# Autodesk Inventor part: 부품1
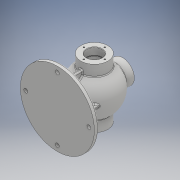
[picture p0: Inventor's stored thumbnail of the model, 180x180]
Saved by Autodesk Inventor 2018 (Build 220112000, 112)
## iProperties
Created: 2020-08
Part Number: 부품1
Material: Generic
Document SubType Name: Modeling
Designer: Administrator
Density: 1 g/cm^3
Appearance: Default
Author: Administrator
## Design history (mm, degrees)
sketch "스케치1"
  geometry: L1 (-85, 0)-(-85, 85); L2 (-85, 85)-(-75, 85); L3 (-75, 85)-(-75, 0); L4 (-75, 0)-(-85, 0); L5 (53, 0)-(-53, 0); A1 r 53 centre (0, 0) between (53, 0) and (-53, 0); 1 further point
  constraints: 10 end point, 2 horizontal, 2 point on circle, 1 centre point, 1 coincident, 1 perpendicular, 1 vertical
  dimensions: "d2" = 85 distance of L1.start L1.end; "d3" = 10 distance of L1.end L2.end
revolve "회전1" sketch "스케치1" stored, may be unused: angle "d4" = 90 deg
sketch "스케치2"
  geometry: L1 (0, 68)-(31, 68); L2 (31, 68)-(31, -68); L3 (31, -68)-(0, -68); L4 (0, 68)-(0, -68); 1 further point
  constraints: 8 end point, 2 perpendicular, 1 vertical
revolve "회전2" sketch "스케치2" stored, may be unused: angle "d9" = 90 deg
sketch "스케치3"
  geometry: L1 (85, -75)-(-85, -75) reference; L2 (43, -75)-(-43, -75); L3 (-43, -75)-(-43, 0); L4 (-43, 0)-(43, 0); L5 (43, 0)-(43, -75); 1 further point
  constraints: 8 end point, 3 perpendicular, 1 point on line
extrude "돌출1" join sketch "스케치3" stored distance "d12" = 8; taper "d13" = 0 deg
sketch "스케치4"
  geometry: L1 (-75, -85)-(-75, 85) reference; L2 (-75, -43.012)-(-75, 43); L3 (-75, 43)-(3.544, 42.988); L4 (-31, 42.988)-(31, 42.988) reference; L5 (3.544, 42.988)-(3.544, -43.012); L6 (3.544, -43.012)-(-75, -43.012); A1 r 4.279 centre (3.544, 38.71) between (3.543, 34.431) and (3.544, 42.988); A2 r 4.279 centre (3.544, 38.71) between (3.544, 42.988) and (3.543, 34.431); 1 further point
  constraints: 8 end point, 4 point on circle, 3 point on line, 3 tangent, 2 centre point, 2 perpendicular
extrude "돌출2" join sketch "스케치4" stored distance "d17" = 8; taper "d18" = 0 deg
sketch "스케치5"
  geometry: L1 (43, 0)-(-43, 0); A1 r 43 centre (0, 0) between (43, 0) and (-43, 0); 1 further point
  constraints: 2 end point, 2 point on circle, 1 centre point, 1 coincident, 1 horizontal
revolve "회전3" sketch "스케치5" stored, may be unused: angle "d20" = 90 deg
sketch "스케치6"
  geometry: L1 (0, 74.444)-(17.5, 74.444); L2 (17.5, 74.444)-(17.5, -78.998); L3 (17.5, -78.998)-(0, -78.998); L4 (0, 74.444)-(0, -78.998); 1 further point
  constraints: 8 end point, 1 perpendicular, 1 vertical
revolve "회전4" sketch "스케치6" stored, may be unused: angle "d23" = 90 deg
sketch "스케치7"
  geometry: L1 (0, 52)-(18.5, 52); L2 (18.5, 52)-(18.5, 50.25); L3 (18.5, 50.25)-(0, 50.25); L4 (0, 50.25)-(0, 52); L5 (0, -52)-(18.5, -52); L6 (18.5, -52)-(18.5, -50.25); L7 (18.5, -50.25)-(0, -50.25); L8 (0, -50.25)-(0, -52); 1 further point
  constraints: 16 end point, 2 perpendicular, 1 horizontal
revolve "회전5" sketch "스케치7" stored, may be unused: angle "d27" = 90 deg
node "작업 평면1"
sketch "스케치8"
  geometry: C1 r 27 at (0, 0); 1 further point
  constraints: 1 centre point, 1 coincident
  dimensions: "d28" = 54 diameter of C1
extrude "돌출3" join sketch "스케치8" stored distance "d29" = 80; taper "d30" = 0 deg
sketch "스케치9"
  geometry: L1 (0, 65)-(-39.777, 65); L2 (-39.777, 65)-(-39.777, 103.189); L3 (-39.777, 103.189)-(41.506, 103.189); L4 (41.506, 103.189)-(41.506, 65); L5 (41.506, 65)-(0, 65); 1 further point
  constraints: 10 end point, 4 perpendicular, 1 horizontal, 1 point on line
  dimensions: "d32" = 81.28308 distance between parallel lines of L2 L4; "d33" = 38.18916 distance between parallel lines of L5 L3; "d34" = 41.50625 distance from line of point (0, 0) L4; "d35" = 65 distance from line of point (0, 0) L5; "d36" = 41.50625 distance from line of L1.start L4
extrude "돌출4" cut sketch "스케치9" distance "d37" = 100; taper "d38" = 0 deg
sketch "스케치10"
  geometry: C1 r 13 at (0, 0); 1 further point
  constraints: 1 centre point, 1 coincident
  dimensions: "d39" = 26 diameter of C1
extrude "돌출5" cut sketch "스케치10" distance "d40" = 50; taper "d41" = 0 deg
sketch "스케치11"
  geometry: C1 r 2 at (-20, 0); 1 further point
  constraints: 1 centre point
  dimensions: "d43" = 4 diameter of C1
hole "구멍1" sketch "스케치11" at (-20, 0) diameter "d44" = 3.242; stored, may be unused: countersink angle "d48" = 90 deg, drill point angle "d50" = 118 deg; dims "d45" = 12, "d46" = 4, "d47" = 2, "d49" = 15
sketch "스케치12"
  geometry: L1 (43, 0)-(-43, 0); A1 r 43 centre (0, 0) between (43, 0) and (-43, 0); 1 further point
  constraints: 2 end point, 2 point on circle, 1 centre point, 1 coincident, 1 horizontal
revolve "회전6" sketch "스케치12" stored, may be unused: angle "d54" = 350 deg
sketch "스케치13"
  geometry: C1 r 4.5 at (-72.5, 0); 2 further points
  constraints: 1 centre point
  dimensions: "d56" = 9 diameter of C1
extrude "돌출6" cut sketch "스케치13" distance "d57" = 50; taper "d58" = 0 deg
sketch "스케치14"
  geometry: L1 (-75, 4)-(-75, -4) reference; L2 (-75, -52)-(-75, 52); L3 (-75, 52)-(-25.941, 52); L4 (-25.941, 52)-(-25.941, -52); L5 (-25.941, -52)-(-75, -52); 1 further point
  constraints: 8 end point, 2 perpendicular, 1 collinear, 1 horizontal
  dimensions: "d63" = 104 distance of L3.end L4.end
extrude "돌출7" join sketch "스케치14" stored distance "d64" = 8; taper "d65" = 0 deg
sketch "스케치15"
  geometry: L1 (43, 0)-(-43, 0); A1 r 43 centre (0, 0) between (43, 0) and (-43, 0); 1 further point
  constraints: 2 end point, 2 point on circle, 1 centre point, 1 coincident, 1 horizontal
revolve "회전7" sketch "스케치15" stored, may be unused: angle "d66" = 350 deg
fillet "모깎기1" dims "d67" = 3
fillet "모깎기2" dims "d68" = 3
chamfer "모따기1" distance "d69" = 1; stored, may be unused: second distance "d70" = 2, angle "d71" = 45 deg
sketch "스케치16"
  geometry: C1 r 2 at (0, 24); 1 further point
  constraints: 1 centre point
  dimensions: "d73" = 4 diameter of C1
hole "구멍2" sketch "스케치16" at (0, 24) diameter "d75" = 3.242; stored, may be unused: countersink angle "d79" = 90 deg, drill point angle "d81" = 118 deg; dims "d76" = 12, "d77" = 4, "d78" = 2, "d80" = 15
node "작업 평면2"
node "작업 평면3"
sketch "스케치17"
  geometry: L1 (-12, -27)-(-12, 27) reference; L2 (-12, -27)-(-12, 0); L3 (-12, 0)-(-3, 0); 2 further points
  constraints: 4 end point, 1 coincident, 1 midpoint, 1 perpendicular, 1 other
  dimensions: "d85" = 27 distance of L1.start L2.end (derived); "d86" = 9 distance of L2.end L3.end
feature "엠보싱1" sketch "스케치17" dims "d13" = 0, "d87" = 0.5, "d88" = 0
node "솔리드1"
pattern_circular "원형 패턴1" dims angle "d52" = 360 deg
pattern_circular "원형 패턴2" dims angle "d60" = 360 deg
pattern_circular "원형 패턴3" dims angle "d83" = 360 deg
mirror "미러1"
